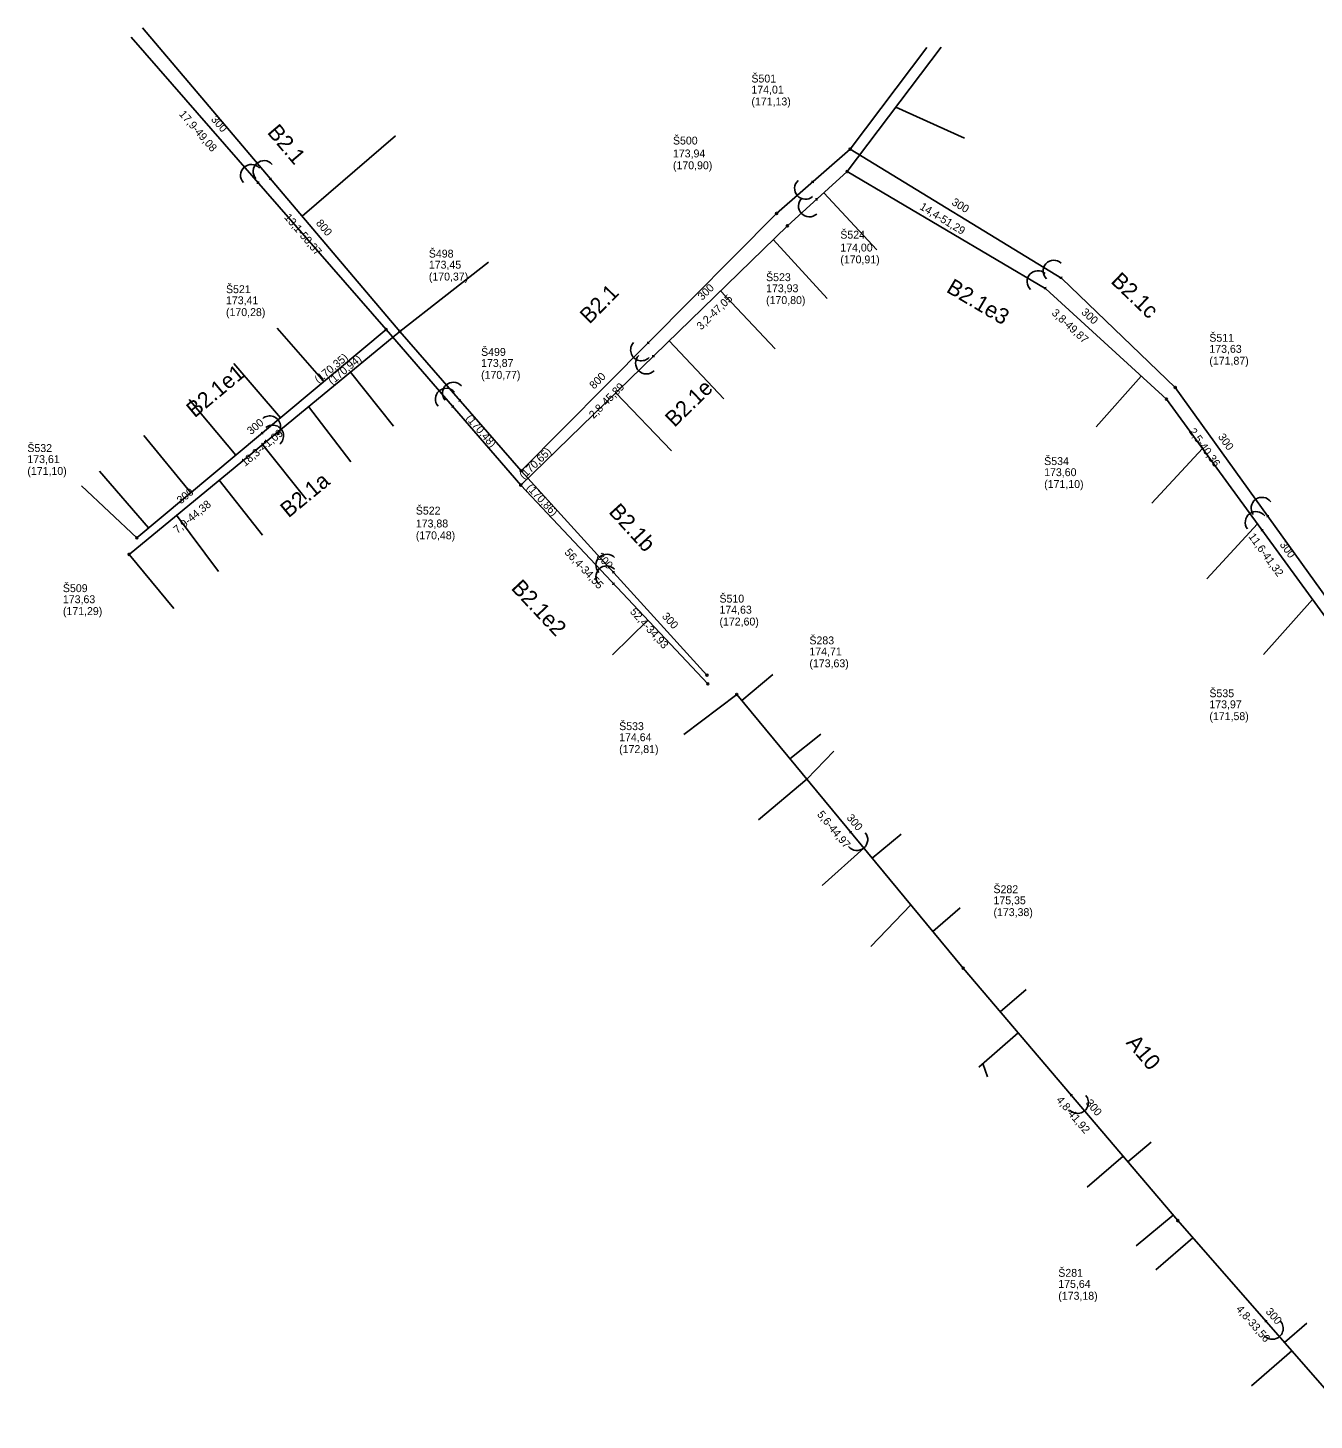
# Model space of a CAD drawing. Extents: x -548529 to -543591, y -1201432 to -1192608.
# Drawn here: x -544450.3 to -544287.5, y -1192839.5 to -1192663.3 of the extents above; entities that cross this region are included whole.
import ezdxf

# ---------------------------------------------------------------- set-up
doc = ezdxf.new("R2010")
doc.units = 0
for name, color, linetype in [('C3D_Bod-Značky', 7, 'Continuous'), ('C3D_Koridor', 7, 'Continuous'), ('C3D_Křižovatka', 7, 'Continuous'), ('C3D_Netisknutelná', 7, 'Continuous'), ('C3D_PP-zobrazeni v PR', 7, 'Continuous'), ('C3D_PR-Popisek', 7, 'Continuous'), ('C3D_SPR-Popisek', 7, 'Continuous'), ('C3D_Tlakove_potrubi_Popis', 7, 'Continuous'), ('C3D_ZPR-Formaty', 7, 'Continuous')]:
    doc.layers.add(name, color=color, linetype=linetype)

# ---------------------------------------------------------------- blocks, each defined once
blk = doc.blocks.new('100')
at = {"layer": 'Defpoints'}
blk.add_circle((0, 0), 0.127, dxfattribs=at)
blk = doc.blocks.new('86')
at = {"layer": 'Defpoints'}
blk.add_lwpolyline([(0.08, 0.14), (0.19, 0), (0.08, -0.14)], dxfattribs=at)
blk.add_arc((1.37, 0), 1.37, 270, 90, dxfattribs=at)
blk = doc.blocks.new('91')
at = {"layer": 'Defpoints'}
blk.add_lwpolyline([(0.08, 0.14), (0.19, 0), (0.08, -0.14)], dxfattribs=at)
blk.add_arc((1.37, 0), 1.37, 270, 90, dxfattribs=at)

msp = doc.modelspace()

# ---------------------------------------------------------------- linework, layer by layer
at = {"layer": 'C3D_Bod-Značky'}
for points in [[(-544403.191, -1192701.675), (-544435.77, -1192663.26)], [(-544404.936, -1192701.446), (-544437.18, -1192664.45)], [(-544334.68, -1192665.698), (-544346.589, -1192681.447)], [(-544336.507, -1192665.755), (-544346.206, -1192678.597)], [(-544346.206, -1192678.597), (-544355.514, -1192686.746)], [(-544305.076, -1192708.764), (-544319.432, -1192694.974), (-544346.206, -1192678.597)], [(-544346.589, -1192681.447), (-544354.162, -1192688.316)], [(-544306.195, -1192710.243), (-544321.448, -1192696.28), (-544346.589, -1192681.447)], [(-544355.514, -1192686.746), (-544387.83, -1192719.325)], [(-544354.162, -1192688.316), (-544387.899, -1192721.115)], [(-544437.453, -1192729.891), (-544403.191, -1192701.675)], [(-544436.469, -1192727.789), (-544404.936, -1192701.446)], [(-544387.899, -1192721.115), (-544404.936, -1192701.446)], [(-544387.83, -1192719.325), (-544403.191, -1192701.675)], [(-544281.526, -1192741.543), (-544305.076, -1192708.764)], [(-544281.861, -1192743.64), (-544306.195, -1192710.243)], [(-544364.328, -1192745.166), (-544387.83, -1192719.325)], [(-544364.232, -1192746.285), (-544387.899, -1192721.115)], [(-544360.57, -1192747.62), (-544331.91, -1192782.27)], [(-544331.91, -1192782.27), (-544304.76, -1192814.21)], [(-544304.76, -1192814.21), (-544282.66, -1192839.46)]]:
    msp.add_lwpolyline(points, dxfattribs=at)
at = {"layer": 'C3D_Koridor'}
for points in [[(-544340.43, -1192673.303), (-544331.752, -1192677.202)], [(-544415.547, -1192687.105), (-544403.72, -1192676.935)], [(-544349.561, -1192684.143), (-544342.824, -1192691.349)], [(-544355.96, -1192690.064), (-544349.117, -1192697.526)], [(-544403.191, -1192701.675), (-544391.993, -1192692.922)], [(-544362.635, -1192696.554), (-544355.716, -1192703.902)], [(-544412.809, -1192708.024), (-544418.708, -1192701.282)], [(-544369.121, -1192702.859), (-544362.186, -1192710.207)], [(-544418.31, -1192712.619), (-544424.21, -1192705.735)], [(-544409.448, -1192706.828), (-544404.002, -1192713.679)], [(-544309.373, -1192707.333), (-544315.095, -1192713.751)], [(-544375.881, -1192709.431), (-544368.811, -1192716.771)], [(-544423.963, -1192717.341), (-544429.858, -1192710.287)], [(-544414.746, -1192711.191), (-544409.407, -1192718.183)], [(-544429.653, -1192722.095), (-544435.575, -1192714.868)], [(-544420.589, -1192716.002), (-544415.056, -1192722.887)], [(-544301.632, -1192716.505), (-544308.061, -1192723.406)], [(-544434.975, -1192726.541), (-544441.207, -1192719.38)], [(-544426.04, -1192720.492), (-544420.561, -1192727.466)], [(-544436.469, -1192727.789), (-544443.482, -1192721.202)], [(-544431.432, -1192724.932), (-544426.133, -1192732.068)], [(-544294.685, -1192726.04), (-544301.079, -1192732.97)], [(-544437.453, -1192729.891), (-544431.795, -1192736.751)], [(-544287.706, -1192735.618), (-544293.904, -1192742.554)], [(-544371.826, -1192738.209), (-544376.271, -1192742.606)], [(-544359.92, -1192748.406), (-544356.008, -1192745.097)], [(-544360.57, -1192747.62), (-544367.255, -1192752.672)], [(-544353.839, -1192755.757), (-544349.938, -1192752.654)], [(-544351.711, -1192758.331), (-544348.28, -1192754.789)], [(-544351.711, -1192758.331), (-544357.824, -1192763.482)], [(-544343.432, -1192768.34), (-544339.776, -1192765.298)], [(-544344.464, -1192767.093), (-544349.759, -1192771.787)], [(-544338.537, -1192774.258), (-544343.609, -1192779.523)], [(-544335.772, -1192777.601), (-544332.297, -1192774.609)], [(-544327.234, -1192787.771), (-544323.947, -1192784.96)], [(-544324.954, -1192790.453), (-544329.937, -1192794.789)], [(-544329.413, -1192794.334), (-544328.833, -1192796.022)], [(-544311.075, -1192806.781), (-544308.116, -1192804.262)], [(-544311.684, -1192806.065), (-544316.218, -1192809.991)], [(-544305.362, -1192813.501), (-544310.023, -1192817.384)], [(-544302.85, -1192816.392), (-544307.546, -1192820.425)], [(-544291.246, -1192829.651), (-544288.45, -1192827.189)], [(-544290.323, -1192830.704), (-544295.45, -1192835.129)]]:
    msp.add_lwpolyline(points, dxfattribs=at)

# ---------------------------------------------------------------- block references
at = {"layer": 'C3D_PP-zobrazeni v PR'}
for p, xscale, yscale, rotation in [((-544346.206, -1192678.597), 1.0000000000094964, 1.0000000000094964, -132.0000013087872), ((-544346.589, -1192681.447), 1.0000000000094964, 1.0000000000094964, -132.0000013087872), ((-544355.514, -1192686.746), 1.0000000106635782, 1.0000000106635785, -135.99999834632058), ((-544354.162, -1192688.316), 1.0000000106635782, 1.0000000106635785, -135.99999834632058), ((-544404.936, -1192701.446), 1.0000000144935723, 1.0000000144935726, 130.99999910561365), ((-544403.191, -1192701.675), 1.0000000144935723, 1.0000000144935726, 130.99999910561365), ((-544306.195, -1192710.243), 1.0000000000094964, 1.0000000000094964, 132.0000013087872), ((-544305.076, -1192708.764), 1.0000000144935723, 1.0000000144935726, 130.99999910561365), ((-544387.83, -1192719.325), 1.0000000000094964, 1.0000000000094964, 132.0000013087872), ((-544387.899, -1192721.115), 1.00000000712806, 1.00000000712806, 133.00000056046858), ((-544436.469, -1192727.789), 1.0000000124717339, 1.0000000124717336, -139.99999868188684), ((-544437.453, -1192729.891), 1.0000000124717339, 1.0000000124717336, -139.99999868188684), ((-544364.328, -1192745.166), 1.00000000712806, 1.00000000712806, -46.99999943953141), ((-544364.232, -1192746.285), 1.0000000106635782, 1.0000000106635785, -45.99999834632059), ((-544360.57, -1192747.62), 1.0000000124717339, 1.0000000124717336, -49.99999868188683), ((-544331.91, -1192782.27), 1.0000000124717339, 1.0000000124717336, 130.0000013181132), ((-544304.76, -1192814.21), 1.0000000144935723, 1.0000000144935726, 130.99999910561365)]:
    msp.add_blockref('100', p, dxfattribs=dict(at, xscale=xscale, yscale=yscale, rotation=rotation))
at = {"layer": 'C3D_SPR-Popisek'}
for name, p, xscale, yscale, rotation in [('86', (-544421.058, -1192682.948), 1.0000000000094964, 1.0000000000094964, 132.0000013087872), ('86', (-544419.481, -1192682.468), 1.0000000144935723, 1.0000000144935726, 130.99999910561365), ('86', (-544350.86, -1192682.672), 1.0000000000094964, 1.0000000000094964, -137.9999986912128), ('86', (-544350.376, -1192684.882), 1.00000000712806, 1.00000000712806, -136.99999943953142), ('86', (-544319.432, -1192694.974), 1.00000000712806, 1.00000000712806, 136.99999943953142), ('86', (-544321.448, -1192696.28), 1.0000000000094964, 1.0000000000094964, 137.9999986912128), ('86', (-544371.672, -1192703.036), 1.0000000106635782, 1.0000000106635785, -134.00000165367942), ('86', (-544371.03, -1192704.716), 0.999999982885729, 0.9999999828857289, -135), ('86', (-544396.418, -1192711.28), 1.0000000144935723, 1.0000000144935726, 130.99999910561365), ('86', (-544395.51, -1192710.5), 1.0000000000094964, 1.0000000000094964, 132.0000013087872), ('86', (-544420.702, -1192714.618), 1.0000000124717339, 1.0000000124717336, 40.00000131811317), ('86', (-544420.322, -1192715.783), 1.0000000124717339, 1.0000000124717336, 40.00000131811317), ('86', (-544293.301, -1192725.154), 1.000000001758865, 1.000000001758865, 125.99999933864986), ('86', (-544294.028, -1192726.942), 0.9999999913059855, 0.9999999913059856, 127.00000193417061), ('86', (-544376.079, -1192732.246), 1.00000000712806, 1.00000000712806, 133.00000056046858), ('86', (-544376.066, -1192733.7), 1.0000000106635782, 1.0000000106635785, 134.00000165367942), ('91', (-544346.24, -1192764.945), 1.0000000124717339, 1.0000000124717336, -49.99999868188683), ('91', (-544318.335, -1192798.24), 1.0000000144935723, 1.0000000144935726, -49.00000089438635), ('91', (-544293.71, -1192826.835), 1.0000000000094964, 1.0000000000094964, -47.99999869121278)]:
    msp.add_blockref(name, p, dxfattribs=dict(at, xscale=xscale, yscale=yscale, rotation=rotation))

# ---------------------------------------------------------------- texts
at = {"layer": 'C3D_Křižovatka'}
for s, p in [('Š501', (-544358.706, -1192670.177)), ('Š500', (-544368.634, -1192678.026)), ('Š524', (-544347.459, -1192689.937)), ('Š498', (-544399.521, -1192692.335)), ('Š523', (-544356.852, -1192695.316)), ('Š521', (-544425.186, -1192696.836)), ('Š511', (-544300.766, -1192702.984)), ('Š499', (-544392.91, -1192704.775)), ('Š532', (-544450.319, -1192716.939)), ('Š534', (-544321.665, -1192718.593)), ('Š522', (-544401.169, -1192724.855)), ('Š509', (-544445.823, -1192734.671)), ('Š510', (-544362.748, -1192735.996)), ('Š283', (-544351.37, -1192741.28)), ('Š535', (-544300.761, -1192747.97)), ('Š533', (-544375.442, -1192752.135)), ('Š282', (-544328.08, -1192772.77)), ('Š281', (-544319.88, -1192821.32))]:
    msp.add_text(s, height=1, dxfattribs=at).set_placement(p)
at = {"layer": 'C3D_Netisknutelná'}
for s, rotation, p in [('B2.1', 310.3, (-544420.057, -1192676.528)), ('B2.1c', 316.15, (-544313.336, -1192695.45)), ('B2.1', 45.23, (-544379.204, -1192700.833)), ('B2.1e3', 329.46, (-544334.167, -1192696.619)), ('B2.1e1', 39.88, (-544429.154, -1192712.684)), ('B2.1e', 44.19, (-544368.444, -1192713.895)), ('B2.1a', 39.47, (-544417.276, -1192725.348)), ('B2.1b', 312.29, (-544376.862, -1192724.579)), ('B2.1e2', 313.24, (-544389.214, -1192734.239)), ('A10', 310.37, (-544311.389, -1192791.73))]:
    msp.add_text(s, height=2, rotation=rotation, dxfattribs=at).set_placement(p)
at = {"layer": 'C3D_PR-Popisek'}
for s, rotation, p in [('300', 311.07, (-544427.152, -1192674.885)), ('300', 328.55, (-544333.46, -1192685.57)), ('800', 310.3, (-544413.869, -1192688.008)), ('300', 44.19, (-544364.941, -1192697.816)), ('300', 317.53, (-544317.051, -1192699.353)), ('800', 45.23, (-544378.618, -1192709.052)), ('300', 39.88, (-544422.024, -1192714.814)), ('300', 305.7, (-544299.715, -1192715.022)), ('300', 39.47, (-544430.902, -1192723.584)), ('300', 306.08, (-544291.917, -1192728.66)), ('300', 313.24, (-544378.381, -1192730.223)), ('300', 312.29, (-544370.095, -1192737.78)), ('300', 309.6, (-544346.724, -1192763.254)), ('300', 310.37, (-544316.47, -1192799.359)), ('300', 311.19, (-544293.708, -1192825.77))]:
    msp.add_text(s, height=1, rotation=rotation, dxfattribs=at).set_placement(p)
at = {"layer": 'C3D_Tlakove_potrubi_Popis'}
for s, p in [('174,01 ', (-544358.706, -1192671.577)), ('(171,13)', (-544358.706, -1192673.077)), ('(170,90)', (-544368.634, -1192681.156)), ('173,94 ', (-544368.634, -1192679.656)), ('174,00 ', (-544347.459, -1192691.567)), ('(170,91)', (-544347.459, -1192693.067)), ('(170,37)', (-544399.521, -1192695.235)), ('173,45 ', (-544399.521, -1192693.735)), ('173,93 ', (-544356.852, -1192696.716)), ('173,41 ', (-544425.186, -1192698.236)), ('(170,80)', (-544356.852, -1192698.216)), ('(170,28)', (-544425.186, -1192699.736)), ('(171,87)', (-544300.766, -1192705.884)), ('173,63 ', (-544300.766, -1192704.384)), ('173,87 ', (-544392.91, -1192706.175)), ('(170,77)', (-544392.91, -1192707.675)), ('(171,10)', (-544450.319, -1192719.839)), ('173,61 ', (-544450.319, -1192718.339)), ('(171,10)', (-544321.665, -1192721.493)), ('173,60 ', (-544321.665, -1192719.993)), ('173,88 ', (-544401.169, -1192726.485)), ('(170,48)', (-544401.169, -1192727.985)), ('(171,29)', (-544445.823, -1192737.571)), ('173,63 ', (-544445.823, -1192736.071)), ('174,63 ', (-544362.748, -1192737.396)), ('(172,60)', (-544362.748, -1192738.896)), ('174,71 ', (-544351.37, -1192742.68)), ('(173,63)', (-544351.37, -1192744.18)), ('173,97 ', (-544300.761, -1192749.37)), ('(171,58)', (-544300.761, -1192750.87)), ('(172,81)', (-544375.442, -1192755.035)), ('174,64 ', (-544375.442, -1192753.535)), ('175,35 ', (-544328.08, -1192774.17)), ('(173,38)', (-544328.08, -1192775.67)), ('175,64 ', (-544319.88, -1192822.72)), ('(173,18)', (-544319.88, -1192824.22))]:
    msp.add_text(s, height=1, dxfattribs=at).set_placement(p)
at = {"layer": 'C3D_ZPR-Formaty'}
for s, rotation, p in [('17,9-49,08', 311.07, (-544431.187, -1192674.22)), ('13,1-50,37', 310.3, (-544417.884, -1192687.281)), ('14,4-51,29', 328.55, (-544337.508, -1192686.151)), ('3,2-47,05', 44.19, (-544365.062, -1192701.561)), ('3,8-49,87', 317.53, (-544320.798, -1192699.453)), ('  (170,35)   ', 39.88, (-544414.043, -1192708.794)), ('  (170,94)   ', 39.47, (-544412.35, -1192708.958)), ('2,8-45,89', 45.23, (-544378.675, -1192712.794)), ('  (170,48)   ', 310.9, (-544395.408, -1192712.141)), ('18,3-41,09', 39.88, (-544422.774, -1192718.828)), ('2,5-40,36', 305.7, (-544303.408, -1192714.346)), ('  (170,65)   ', 44.19, (-544388.038, -1192720.972)), ('  (170,86)   ', 313.24, (-544387.753, -1192720.978)), ('7,9-44,38', 39.47, (-544431.337, -1192727.311)), ('11,6-41,32', 306.08, (-544295.874, -1192727.639)), ('56,4-34,55', 313.24, (-544382.429, -1192729.707)), ('52,4-34,93', 312.29, (-544374.141, -1192737.202)), ('5,6-44,97', 309.6, (-544350.454, -1192762.836)), ('4,8-41,92', 310.37, (-544320.196, -1192798.979)), ('4,8-33,56', 311.19, (-544297.449, -1192825.45))]:
    msp.add_text(s, height=1, rotation=rotation, dxfattribs=at).set_placement(p)

doc.saveas('drawing.dxf')
